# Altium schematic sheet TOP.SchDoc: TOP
size A4; Author: Daniela Catanzaro; CompanyName: Arduino srl; DocumentNumber: ASX00055; SheetNumber: 1; SheetTotal: 10; RevAuthor: Daniela Catanzaro
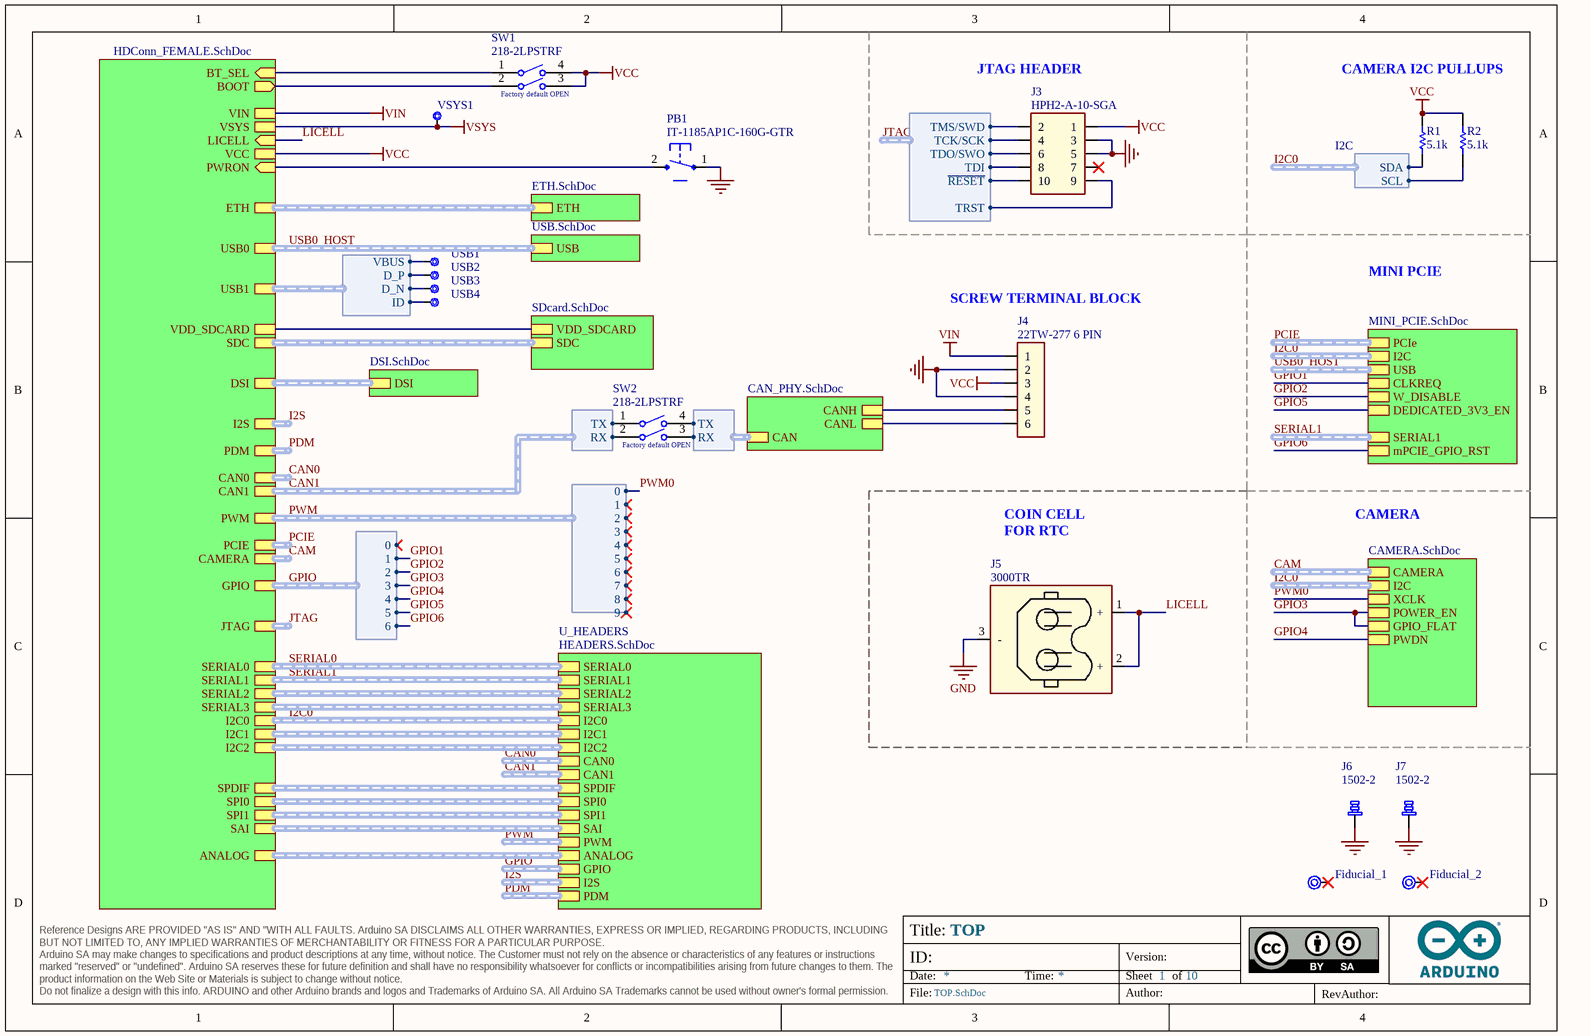
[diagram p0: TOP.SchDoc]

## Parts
Fiducial_1  Fiducial mark 1mm with 2mm solder  [Fiducial mark 1mm with circle-Footprint-1]  (value not drawn)  (no BOM)
Fiducial_2  Fiducial mark 1mm with 2mm solder  [Fiducial mark 1mm with circle-Footprint-1]  (value not drawn)  (no BOM)
J3  HPH2-A-10-SGA  [PINHEAD_2X05_127]
J4  22TW-277 6 PIN  [22TW-277 6 PIN]
J5  3000TR  [3000TR-Footprint-1]
J6  1502-2  [1502-2]
J7  1502-2  [1502-2]
PB1  IT-1185AP1C-160G-GTR  [C&K_PTS820_NO_HOLES-1]
R1  value 5.1k  [RES-0402]  (hidden comment: RC0402FR-075K1L)
R2  value 5.1k  [RES-0402]  (hidden comment: RC0402FR-075K1L)
SW1  218-2LPSTRF  [CTS-218-2LPST_V]
SW2  218-2LPSTRF  [CTS-218-2LPST_V]
USB1  Test point 1.00mm  [TP-1.00MM]  (value not drawn)  (no BOM)
USB2  Test point 1.00mm  [TP-1.00MM]  (value not drawn)  (no BOM)
USB3  Test point 1.00mm  [TP-1.00MM]  (value not drawn)  (no BOM)
USB4  Test point 1.00mm  [TP-1.00MM]  (value not drawn)  (no BOM)
VSYS1  Test point 1.00mm  [TP-1.00MM]  (value not drawn)  (no BOM)

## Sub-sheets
HDConnectors FEMALE = HDConn_FEMALE.SchDoc: PWRON (in), BOOT (out), USB1 (harness USB), SERIAL0 (harness UART), SAI (harness SAI), I2C2 (harness I2C), USB0 (harness USB), JTAG (harness JTAG), BT_SEL (in), I2S (harness I2S), I2C0 (harness I2C), ETH (harness ETH), PWM (harness PWM), I2C1 (harness I2C), GPIO (harness GPIO), SPI1 (harness SPI), VCC, SERIAL3 (harness UART), CAMERA (harness CAMERA), LICELL (in), PDM (harness PDM), DSI (harness DISPLAY), CAN1 (harness CAN), SDC (harness SDC), SERIAL2 (harness UART), ANALOG (harness ANALOG), SERIAL1 (harness UART), VIN, VSYS, CAN0 (harness CAN), SPI0 (harness SPI), PCIE (harness PCIE), SPDIF (harness SPDIF), VDD_SDCARD
U_CAMERA = CAMERA.SchDoc: I2C (harness I2C), CAMERA (harness CAMERA), GPIO_FLAT, POWER_EN, PWDN, XCLK
U_CAN_PHY = CAN_PHY.SchDoc: CAN (harness CAN), CANH, CANL
U_DSI = DSI.SchDoc: DSI (harness DISPLAY)
U_ETH = ETH.SchDoc: ETH (harness ETH)
U_HEADERS = HEADERS.SchDoc: SERIAL0 (harness UART), SERIAL1 (harness UART), SERIAL2 (harness UART), SERIAL3 (harness UART), I2C0 (harness I2C), CAN0 (harness CAN), SPDIF (harness SPDIF), SPI0 (harness SPI), I2C2 (harness I2C), SAI (harness SAI), PWM (harness PWM), ANALOG (harness ANALOG), SPI1 (harness SPI), GPIO (harness GPIO), CAN1 (harness CAN), I2C1 (harness I2C), I2S (harness I2S), PDM (harness PDM)
U_MINI_PCIE = MINI_PCIE.SchDoc: USB (harness USB), PCIe (harness PCIE), CLKREQ, W_DISABLE, DEDICATED_3V3_EN, SERIAL1 (harness UART), mPCIE_GPIO_RST, I2C (harness PCIE)
U_SDcard = SDcard.SchDoc: SDC (harness SDC), VDD_SDCARD
U_USB = USB.SchDoc: USB (harness USB)

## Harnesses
JTAG: ~{RESET}, TCK/SCK, TDI, TDO/SWO, TMS/SWD, TRST
CAN: RX, TX
I2C: SDA, SCL
GPIO: 0, 1, 2, 3, 4, 5, 6
PWM: 0, 1, 2, 3, 4, 5, 6, 7, 8, 9
USB: VBUS, D_P, D_N, ID

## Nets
GND: J3.3 J3.5 J4.2 J4.4 J5.3(-) J6.1 J7.1 PB1.1
VCC: J3.1 J4.3 R1.2 R2.2 SW1.3 SW1.4 ; sheet HDConnectors FEMALE/VCC
VIN: J4.1 ; sheet HDConnectors FEMALE/VIN
VSYS: VSYS1.X ; sheet HDConnectors FEMALE/VSYS
CAN1.RX: SW2.2 ; sheet HDConnectors FEMALE/CAN1.RX
CAN1.TX: SW2.1 ; sheet HDConnectors FEMALE/CAN1.TX
GPIO1: sheet U_MINI_PCIE/CLKREQ, sheet HDConnectors FEMALE/GPIO.1  [project net GPIO.1]
GPIO2: sheet U_MINI_PCIE/W_DISABLE, sheet HDConnectors FEMALE/GPIO.2  [project net GPIO.2]
GPIO3: sheet U_CAMERA/GPIO_FLAT, sheet U_CAMERA/POWER_EN, sheet HDConnectors FEMALE/GPIO.3  [project net GPIO.3]
GPIO4: sheet U_CAMERA/PWDN, sheet HDConnectors FEMALE/GPIO.4  [project net GPIO.4]
GPIO5: sheet U_MINI_PCIE/DEDICATED_3V3_EN, sheet HDConnectors FEMALE/GPIO.5  [project net GPIO.5]
GPIO6: sheet U_MINI_PCIE/mPCIE_GPIO_RST, sheet HDConnectors FEMALE/GPIO.6  [project net GPIO.6]
I2C0.SCL: R2.1 ; sheet HDConnectors FEMALE/I2C0.SCL
I2C0.SDA: R1.1 ; sheet HDConnectors FEMALE/I2C0.SDA
JTAG.~{RESET}: J3.10 ; sheet HDConnectors FEMALE/JTAG.~{RESET}
JTAG.TCK/SCK: J3.4 ; sheet HDConnectors FEMALE/JTAG.TCK/SCK
JTAG.TDI: J3.8 ; sheet HDConnectors FEMALE/JTAG.TDI
JTAG.TDO/SWO: J3.6 ; sheet HDConnectors FEMALE/JTAG.TDO/SWO
JTAG.TMS/SWD: J3.2 ; sheet HDConnectors FEMALE/JTAG.TMS/SWD
JTAG.TRST: J3.9 ; sheet HDConnectors FEMALE/JTAG.TRST
LICELL: J5.1(+) J5.2(+) ; sheet HDConnectors FEMALE/LICELL
PWM0: sheet U_CAMERA/XCLK, sheet HDConnectors FEMALE/PWM.0  [project net PWM.0]
NetJ4_5: J4.5 ; sheet U_CAN_PHY/CANH
NetJ4_6: J4.6 ; sheet U_CAN_PHY/CANL
NetPB1_2: PB1.2 ; sheet HDConnectors FEMALE/PWRON
NetSW1_1: SW1.1 ; sheet HDConnectors FEMALE/BT_SEL
NetSW1_2: SW1.2 ; sheet HDConnectors FEMALE/BOOT
NetSW2_3: SW2.3 ; sheet U_CAN_PHY/CAN.RX
NetSW2_4: SW2.4 ; sheet U_CAN_PHY/CAN.TX
NetUSB1_X: USB1.X ; sheet HDConnectors FEMALE/USB1.VBUS
NetUSB2_X: USB2.X ; sheet HDConnectors FEMALE/USB1.D_P
NetUSB3_X: USB3.X ; sheet HDConnectors FEMALE/USB1.D_N
NetUSB4_X: USB4.X ; sheet HDConnectors FEMALE/USB1.ID
(unnamed): sheet HDConnectors FEMALE/VDD_SDCARD, sheet U_SDcard/VDD_SDCARD

Not connected (* = marked no-connect by the designer): Fiducial_1 1*; Fiducial_2 1*; J3 7*

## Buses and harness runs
harness CAM = sheet HDConnectors FEMALE/CAMERA
harness CAM = sheet U_CAMERA/CAMERA
harness CAN0 = sheet HDConnectors FEMALE/CAN0
harness CAN0 = sheet U_HEADERS/CAN0
harness CAN1 = sheet HDConnectors FEMALE/CAN1
harness CAN1 = sheet U_HEADERS/CAN1
harness GPIO = sheet HDConnectors FEMALE/GPIO
harness GPIO = sheet U_HEADERS/GPIO
harness I2C0 = sheet HDConnectors FEMALE/I2C0 = sheet U_HEADERS/I2C0
harness I2C0 = sheet U_CAMERA/I2C
harness I2C0 = sheet U_MINI_PCIE/I2C
harness I2S = sheet HDConnectors FEMALE/I2S
harness I2S = sheet U_HEADERS/I2S
harness JTAG = sheet HDConnectors FEMALE/JTAG
harness PCIE = sheet HDConnectors FEMALE/PCIE
harness PCIE = sheet U_MINI_PCIE/PCIe
harness PDM = sheet HDConnectors FEMALE/PDM
harness PDM = sheet U_HEADERS/PDM
harness PWM = sheet HDConnectors FEMALE/PWM
harness PWM = sheet U_HEADERS/PWM
harness SERIAL0 = sheet HDConnectors FEMALE/SERIAL0 = sheet U_HEADERS/SERIAL0
harness SERIAL1 = sheet HDConnectors FEMALE/SERIAL1 = sheet U_HEADERS/SERIAL1
harness SERIAL1 = sheet U_MINI_PCIE/SERIAL1
harness sheet HDConnectors FEMALE/ANALOG = sheet U_HEADERS/ANALOG
harness sheet HDConnectors FEMALE/DSI = sheet U_DSI/DSI
harness sheet HDConnectors FEMALE/ETH = sheet U_ETH/ETH
harness sheet HDConnectors FEMALE/I2C1 = sheet U_HEADERS/I2C1
harness sheet HDConnectors FEMALE/I2C2 = sheet U_HEADERS/I2C2
harness sheet HDConnectors FEMALE/SAI = sheet U_HEADERS/SAI
harness sheet HDConnectors FEMALE/SDC = sheet U_SDcard/SDC
harness sheet HDConnectors FEMALE/SERIAL2 = sheet U_HEADERS/SERIAL2
harness sheet HDConnectors FEMALE/SERIAL3 = sheet U_HEADERS/SERIAL3
harness sheet HDConnectors FEMALE/SPDIF = sheet U_HEADERS/SPDIF
harness sheet HDConnectors FEMALE/SPI0 = sheet U_HEADERS/SPI0
harness sheet HDConnectors FEMALE/SPI1 = sheet U_HEADERS/SPI1
harness USB0_HOST = sheet HDConnectors FEMALE/USB0 = sheet U_USB/USB
harness USB0_HOST = sheet U_MINI_PCIE/USB

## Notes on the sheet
- (near J3) JTAG HEADER
- CAMERA I2C PULLUPS
- (near J4) SCREW TERMINAL BLOCK
- MINI PCIE
- COIN CELL FOR RTC
- CAMERA

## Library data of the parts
Fiducial_1 Fiducial_2 = UT0024-A.6
J3 = J0068-A.9: CONN CONN STRIP THD 1,27 M/2/D 10v AuF H6,3 JTAG; Manufacturer: Adam Tech; Code Arduino: 0171
J4 = J0319-A.4: CONN SCREW TERMINAL 22TW-277 6 PIN BLACK; Manufacturer: 4U CON; Code Arduino: J0319; Number of Contacts: 6; Max Current Rating: 10A
J5 = J0297-A.4: CONN BATT COINCELL SMD CR1225; Manufacturer: Keystone Electronics; Code Arduino: J0297
J6 J7 = J0379-A.2: Turret Connector TH 5,56mm lenght; Manufacturer: Keystone Electronics; Code Arduino: J0379
PB1 = B0001-A.7: PUSHBUTTON WHITE NO ANCHORS; Manufacturer: Switronic; Code Arduino: 0173
R1 R2 = R0210-A.19: RES CHIP 0402 5k1 1% 1/16W; Manufacturer: YAGEO; Power: 62.5mW; Code Arduino: R0210; Temperature coefficient: 100ppm
SW1 SW2 = S0022-A.4: SWITCH DIP NORMALLY OPEN; Manufacturer: CTS Corporation; Number of Positions: 2; Throw Configuration: SPST; Contact Resistance: 100mR; Current Rating: 25mA; Voltage Rating (DC): 24V; Washable: Yes; Pitch: 0.05inch; Electrical Life: 1000Cycles; Actuator Type: Slide (Standard); Code Arduino: S0022
USB1-USB4 VSYS1 = UT0013-A.6: Manufacturer: This is not a component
